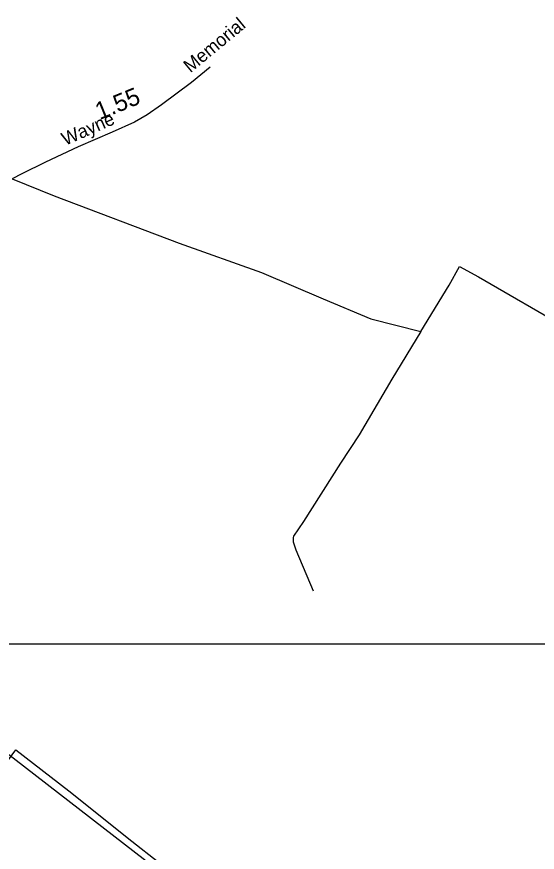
# Model space of a CAD drawing. Extents: x 2315291 to 2336543, y 597177 to 615230.
# Drawn here: x 2325292 to 2329008, y 609266 to 615230 of the extents above; entities that cross this region are included whole.
import ezdxf

# ---------------------------------------------------------------- set-up
doc = ezdxf.new("R2010")
doc.units = 0
for name, color, linetype in [('Exist Hydrographic Creek Single Shore', 7, 'Continuous'), ('Exist Hydrographic Misc Water Feature', 7, 'Continuous'), ('Exist Road Non-System Type 51', 7, 'Continuous'), ('Exist Road Secondary Mileage Hundredths English Label', 7, 'Continuous'), ('Exist Road Secondary Type 51 Attributed', 7, 'Continuous'), ('Exist Road Secondary Type 51 Label', 7, 'Continuous'), ('Map Preparation Inset Cut Line', 7, 'Continuous')]:
    doc.layers.add(name, color=color, linetype=linetype)

msp = doc.modelspace()

# ---------------------------------------------------------------- linework, layer by layer
at = {"layer": 'Exist Hydrographic Creek Single Shore'}
msp.add_lwpolyline([(2326848.4, 608712.7), (2325193.2, 609994.5)], dxfattribs=at)
at = {"layer": 'Exist Hydrographic Misc Water Feature'}
msp.add_lwpolyline([(2324978.5, 609588.1), (2325126.6, 609783.6), (2325286.3, 609997.2), (2325664.8, 609705.5), (2326114.7, 609344.5), (2326489.6, 609050.5)], dxfattribs=at)
at = {"layer": 'Exist Road Non-System Type 51'}
for points in [[(2325259.6, 614073.2), (2325558.1, 613951.5), (2326450.8, 613613.7), (2327039.8, 613403.5), (2327478.6, 613215.8), (2327820, 613073.2), (2328176.3, 612983.1)], [(2328176.3, 612983.1), (2328378.9, 613313.4), (2328453.9, 613448.5), (2328588.9, 613373.5), (2329237.8, 612998.1), (2329853, 612630.3), (2330138.1, 612467)], [(2328176.3, 612983.1), (2327970, 612643.4), (2327737.4, 612245.6), (2327602.4, 612042.9), (2327339.8, 611628.2), (2327268.6, 611523.1), (2327264.8, 611511.8), (2327264.8, 611481.8), (2327283.6, 611425.5), (2327407.3, 611132.7)]]:
    msp.add_lwpolyline(points, dxfattribs=at)
at = {"layer": 'Exist Road Secondary Type 51 Attributed'}
msp.add_lwpolyline([(2326673.8, 614870.5), (2326540.5, 614760.9), (2326325.4, 614600.7), (2326223.7, 614529), (2326132, 614477.3), (2325973.7, 614405.5), (2325730.3, 614300.5), (2325498.5, 614191.2), (2325328.5, 614109.4), (2325259.6, 614073.2)], dxfattribs=at)
at = {"layer": 'Map Preparation Inset Cut Line'}
msp.add_line((2322567.3, 610753.3), (2330518.4, 610753.3), dxfattribs=at)

# ---------------------------------------------------------------- texts
at = {"layer": 'Exist Road Secondary Mileage Hundredths English Label'}
msp.add_text('1.55', height=125, rotation=22.18426, dxfattribs=at).set_placement((2325883.8, 614491.9))
at = {"layer": 'Exist Road Secondary Type 51 Label'}
for s, rotation, p in [('Memorial', 39.5709, (2326531.3, 614826)), ('Wayne', 23.70183, (2325638, 614308.4))]:
    msp.add_text(s, height=95, rotation=rotation, dxfattribs=at).set_placement(p)

doc.saveas('drawing.dxf')
